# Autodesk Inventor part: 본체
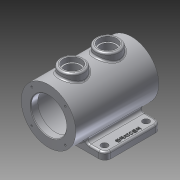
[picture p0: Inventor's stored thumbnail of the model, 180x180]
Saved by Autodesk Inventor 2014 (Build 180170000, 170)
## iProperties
Created: 2014-12
Part Number: 본체
Material: 알루미늄 6061
Document SubType Name: Modeling
Designer: Owner
Density: 2.71 g/cm^3
Appearance: 알루미늄 - 평지
Mass: 1293.91 g
Surface Area: 1040.14 cm^2
Volume: 477.456 cm^3
Author: Owner
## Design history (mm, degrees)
node "작업 평면1"
sketch "스케치2"
  geometry: C1 r 46 at (0, 0); 1 further point
  constraints: 1 centre point, 1 coincident
  dimensions: "d5" = 92 diameter of C1
extrude "돌출2" new body sketch "스케치2" stored distance "d6" = 140; taper "d7" = 0 deg
sketch "스케치3"
  geometry: C1 r 46 at (0, 0) reference; C2 r 30 at (0, 0)
  constraints: 1 centre point, 1 coincident
  dimensions: "d8" = 60 diameter of C2
extrude "돌출3" cut sketch "스케치3" distance "d9" = 12; taper "d10" = 0 deg
sketch "스케치4"
  geometry: C1 r 30 at (0, 0) reference; C2 r 37.5 at (0, 0)
  constraints: 1 centre point, 1 coincident
  dimensions: "d11" = 75 diameter of C2
extrude "돌출4" cut sketch "스케치4" distance "d12" = 70; taper "d13" = 0 deg
node "작업 평면2"
sketch "스케치5"
  geometry: L1 (-65, -40)-(65, -40); L2 (65, -40)-(65, 55); L3 (65, 55)-(-65, 55); L4 (-65, 55)-(-65, -40); L5 (46, 70)-(-46, 70) reference; L6 (-46, -70)-(46, -70) reference; 2 further points
  constraints: 8 end point, 2 parallel, 1 horizontal, 1 midpoint, 1 perpendicular, 1 vertical alignment
  dimensions: "d68" = 30 distance between parallel lines of L1 L6; "d69" = 95 distance of L3.end L1.start; "d70" = 130 distance of L2.end L3.end
extrude "돌출5" join sketch "스케치5" distance "d17" = 12; taper "d18" = 0 deg
node "작업 평면3"
sketch "스케치6"
  geometry: L1 (-25.923, -40)-(25.923, -40) reference; L2 (25.923, -40)-(25.923, 55) reference; L3 (25.923, 55)-(-25.923, 55) reference; L4 (-25.923, 55)-(-25.923, -40) reference; L5 (46, 70)-(-46, 70) reference; L6 (-46, -70)-(46, -70) reference; C1 r 20 at (0, 30); C2 r 20 at (0, -30); 1 further point
  constraints: 2 centre point, 2 vertical alignment
  dimensions: "d20" = 40 diameter of C1; "d21" = 40 diameter of C2; "d22" = 40 distance from line of C2.centre L6; "d23" = 60 distance of C1.centre C2.centre
extrude "돌출6" join sketch "스케치6" stored distance "d24" = 12; taper "d25" = 0 deg
sketch "스케치7"
  geometry: C1 r 20 at (0, 0) reference; C2 r 15 at (0, 0); C3 r 20 at (0, -60) reference; C4 r 15 at (0, -60); 1 further point
  constraints: 2 centre point, 2 coincident
  dimensions: "d26" = 30 diameter of C2; "d27" = 30 diameter of C4
extrude "돌출7" cut sketch "스케치7" distance "d28" = 8; taper "d29" = 0 deg
sketch "스케치8"
  geometry: C1 r 15 at (0, 0) reference; C2 r 12.5 at (0, 0); C3 r 12.5 at (0, -60); 2 further points
  constraints: 2 centre point, 1 coincident, 1 vertical alignment, 1 other
  dimensions: "d30" = 25 diameter of C2; "d32" = 25 diameter of C3; "d33" = 60 distance of C3.centre C1.centre
extrude "돌출8" cut sketch "스케치8" stored distance "d34" = 8; taper "d35" = 0 deg
sketch "스케치10"
  geometry: L1 (1.801, 1.415)-(41.801, 1.415); L2 (0, 0)-(28.284, 28.284); L3 (0, 0)-(40, 0); C1 r 46 at (0, 0) reference; 1 further point
  constraints: 6 end point, 2 horizontal, 1 coincident, 1 equal length
  dimensions: "d43" = 40 distance of L2.start L2.end; "d44" = 45 deg angle of L3 L2
hole "구멍1" sketch "스케치10" at (28.284, 28.284) diameter "d45" = 3.242; stored, may be unused: countersink angle "d49" = 90 deg, drill point angle "d51" = 118 deg; dims "d46" = 8, "d47" = 4, "d48" = 2, "d50" = 10
fillet "모깎기1" dims "d59" = 5
fillet "모깎기2" dims "d60" = 10
fillet "모깎기3" dims "d61" = 3
fillet "모깎기4" dims "d62" = 3
fillet "모깎기5" dims "d63" = 3
chamfer "모따기1" distance "d64" = 1; stored, may be unused: second distance "d65" = 2, angle "d66" = 45 deg
fillet "모깎기6" dims "d67" = 3
sketch "스케치17"
  geometry: L1 (-65, 45)-(-65, -30) reference; L2 (-38.884, 55)-(-55, 55) reference; L3 (55, 55)-(38.884, 55) reference; C1 r 5.5 at (-52, -27.5); C2 r 5.5 at (-52, 42.5); C3 r 12.5 at (0, 30) reference; C4 r 5.5 at (52, 42.5); C5 r 5.5 at (52, -27.5); 1 further point
  constraints: 4 centre point, 2 vertical alignment
  dimensions: "d85" = 11 diameter of C1; "d86" = 11 diameter of C2; "d88" = 12.5 distance from line of C2.centre L2; "d89" = 52 horizontal distance of C3.centre C2.centre; "d90" = 70 distance of C1.centre C2.centre; "d91" = 11 diameter of C4; "d92" = 11 diameter of C5; "d93" = 70 distance of C4.centre C5.centre; "d94" = 52 horizontal distance of C4.centre C3.centre; "d95" = 12.5 distance from line of L3 C4.centre
extrude "돌출11" cut sketch "스케치17" stored distance "d96" = 8; taper "d97" = 0 deg
sketch "스케치18"
  geometry: L1 (65, -30)-(65, 45) reference; C1 r 5.5 at (52, -27.5) reference; 2 further points
  constraints: 1 other
  dimensions: "d98" = 35 vertical distance of point (57, 7.5) C1.centre; "d99" = 8 distance from line of L1 point (57, 7.5)
feature "엠보싱3" sketch "스케치18" dims "d7" = 0, "d100" = 1, "d101" = 0
node "솔리드2"
mirror "대칭1"
pattern_circular "원형 패턴1" dims angle "d53" = 360 deg
mirror "대칭4"
node "투영된 루프1"
node "투영된 루프2"
node "투영된 루프3"
other parameters: "d4" = 0, "d19" = 56
